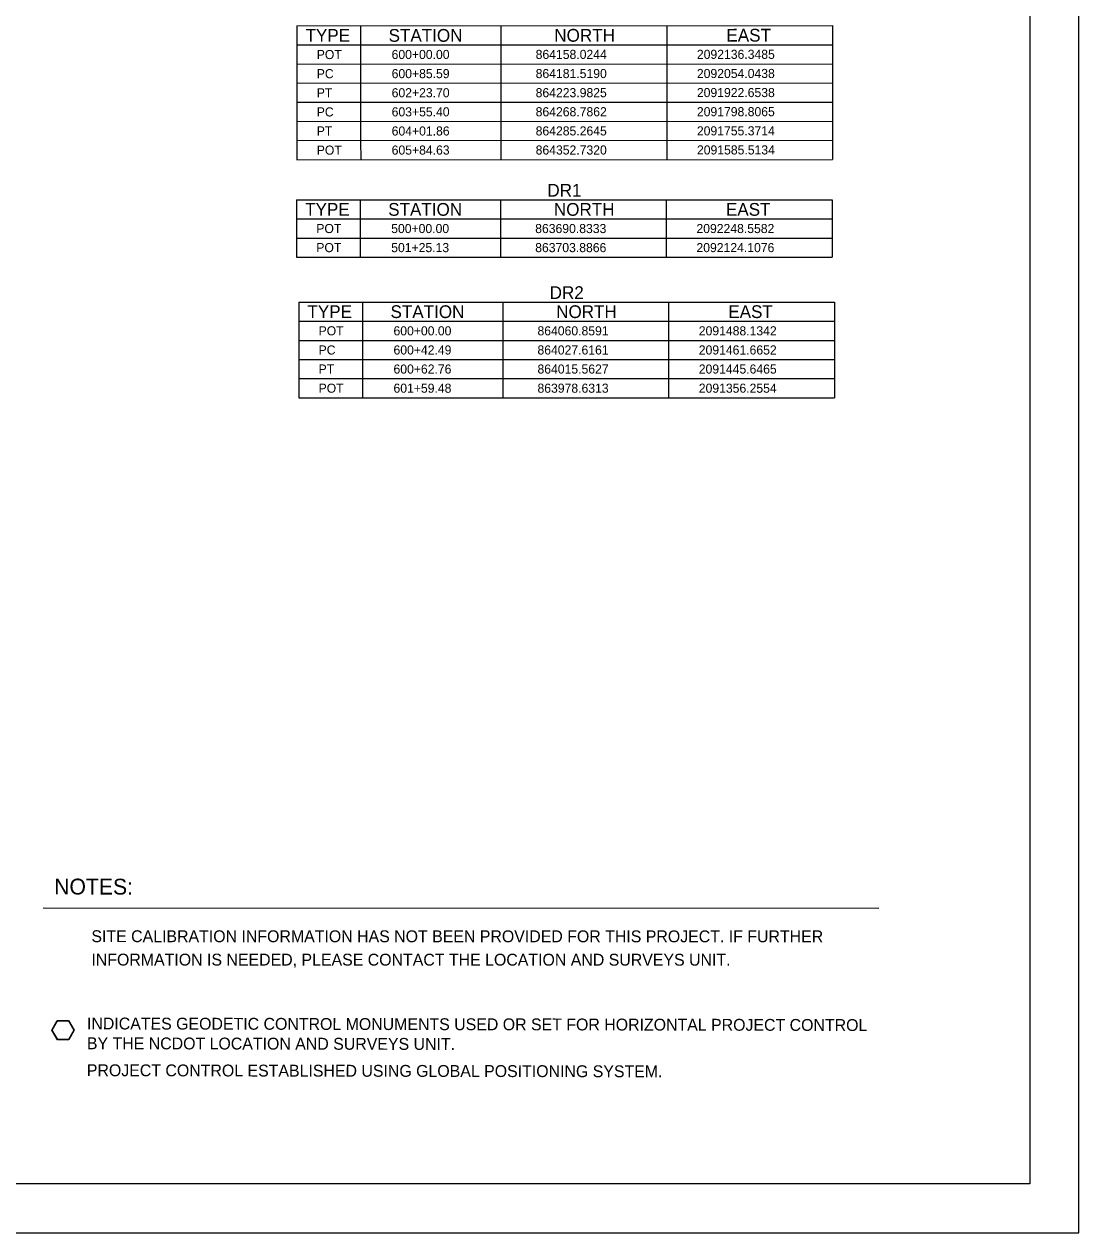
# Model space of a CAD drawing. Extents: x 2093228 to 2098328, y 861854 to 865154.
# Drawn here: x 2096710 to 2098328, y 861854 to 863710 of the extents above; entities that cross this region are included whole.
import ezdxf

# ---------------------------------------------------------------- set-up
doc = ezdxf.new("R2010")
doc.units = 0
for name, color, linetype in [('CTL Primary Horizontal and Vertical CELL', 7, 'Continuous'), ('CTL Sheet Notes CELL', 7, 'Continuous'), ('CTL Sheet Table Cell', 7, 'Continuous'), ('CTL Sheet Text', 7, 'Continuous'), ('Default', 7, 'Continuous'), ('Sheet Plan CELL', 7, 'Continuous'), ('Sheet Plot Border Inside CELL', 7, 'Continuous')]:
    doc.layers.add(name, color=color, linetype=linetype)

msp = doc.modelspace()

# ---------------------------------------------------------------- linework, layer by layer
at = {"layer": 'CTL Primary Horizontal and Vertical CELL'}
msp.add_line((2096769.3, 862165.3), (2096769.3, 862165.3), dxfattribs=at)
msp.add_lwpolyline([(2096777.8, 862180.2), (2096786.3, 862165.4), (2096778.1, 862150.4), (2096761, 862150.5), (2096752.3, 862165.4), (2096760.5, 862180.1)], close=True, dxfattribs=at)
at = {"layer": 'CTL Sheet Notes CELL'}
msp.add_line((2096739, 862353.2), (2098021.6, 862352.9), dxfattribs=at)
at = {"layer": 'CTL Sheet Table Cell'}
for p, q in [((2097128.2, 863707.7), (2097950.3, 863708.1)), ((2097128.2, 863707.7), (2097128.2, 863678.4)), ((2097226.1, 863707.8), (2097226.1, 863678.4)), ((2097441.4, 863707.9), (2097441.4, 863678.5)), ((2097695.8, 863708), (2097695.9, 863678.6)), ((2097950.3, 863708.1), (2097950.3, 863678.8)), ((2097128.2, 863678.4), (2097950.3, 863678.8)), ((2097128.2, 863678.4), (2097128.2, 863649)), ((2097226.1, 863678.4), (2097226.1, 863649.1)), ((2097441.4, 863678.5), (2097441.4, 863649.2)), ((2097695.9, 863678.6), (2097695.9, 863649.3)), ((2097950.3, 863678.8), (2097950.3, 863649.4)), ((2097128.2, 863649), (2097950.3, 863649.4)), ((2097128.2, 863649), (2097128.2, 863619.6)), ((2097226.1, 863649.1), (2097226.1, 863619.7)), ((2097441.4, 863649.2), (2097441.4, 863619.8)), ((2097695.9, 863649.3), (2097695.9, 863619.9)), ((2097950.3, 863649.4), (2097950.4, 863620)), ((2097128.2, 863619.6), (2097950.4, 863620)), ((2097128.2, 863619.6), (2097128.2, 863590.3)), ((2097226.1, 863619.7), (2097226.1, 863590.3)), ((2097441.4, 863619.8), (2097441.4, 863590.4)), ((2097695.9, 863619.9), (2097695.9, 863590.6)), ((2097950.4, 863620), (2097950.4, 863590.7)), ((2097128.2, 863590.3), (2097950.4, 863590.7)), ((2097128.2, 863590.3), (2097128.3, 863560.9)), ((2097226.1, 863590.3), (2097226.1, 863561)), ((2097441.4, 863590.4), (2097441.5, 863561.1)), ((2097695.9, 863590.6), (2097695.9, 863561.2)), ((2097950.4, 863590.7), (2097950.4, 863561.3)), ((2097128.3, 863560.9), (2097950.4, 863561.3)), ((2097441.5, 863561.1), (2097441.5, 863531.7)), ((2097695.9, 863561.2), (2097695.9, 863531.8)), ((2097950.4, 863561.3), (2097950.4, 863532)), ((2097128.3, 863560.9), (2097128.3, 863531.6)), ((2097226.1, 863561), (2097226.1, 863531.6)), ((2097128.3, 863531.6), (2097950.4, 863532)), ((2097128.3, 863531.6), (2097128.3, 863502.2)), ((2097226.1, 863531.6), (2097226.2, 863502.2)), ((2097441.5, 863531.7), (2097441.5, 863502.3)), ((2097695.9, 863531.8), (2097695.9, 863502.5)), ((2097950.4, 863532), (2097950.4, 863502.6)), ((2097128.3, 863502.2), (2097950.4, 863502.6)), ((2097127.6, 863440.6), (2097949.7, 863440.6)), ((2097127.6, 863440.6), (2097127.6, 863411.2)), ((2097225.4, 863440.6), (2097225.4, 863411.2)), ((2097440.7, 863440.6), (2097440.7, 863411.2)), ((2097695.2, 863440.6), (2097695.2, 863411.2)), ((2097949.7, 863440.6), (2097949.7, 863411.2)), ((2097127.6, 863411.2), (2097949.7, 863411.2)), ((2097127.6, 863411.2), (2097127.6, 863381.9)), ((2097225.4, 863411.2), (2097225.4, 863381.9)), ((2097440.7, 863411.2), (2097440.7, 863381.9)), ((2097695.2, 863411.2), (2097695.2, 863381.9)), ((2097949.7, 863411.2), (2097949.7, 863381.9)), ((2097127.6, 863381.9), (2097949.7, 863381.9)), ((2097127.6, 863381.9), (2097127.6, 863352.5)), ((2097225.4, 863381.9), (2097225.4, 863352.5)), ((2097440.7, 863381.9), (2097440.7, 863352.5)), ((2097695.2, 863381.9), (2097695.2, 863352.5)), ((2097949.7, 863381.9), (2097949.7, 863352.5)), ((2097127.6, 863352.5), (2097949.7, 863352.5)), ((2097131.1, 863283.4), (2097953.2, 863283.4)), ((2097131.1, 863283.4), (2097131.1, 863254.1)), ((2097228.9, 863283.4), (2097228.9, 863254.1)), ((2097444.3, 863283.4), (2097444.3, 863254.1)), ((2097698.7, 863283.4), (2097698.7, 863254.1)), ((2097953.2, 863283.4), (2097953.2, 863254.1)), ((2097131.1, 863254.1), (2097953.2, 863254.1)), ((2097131.1, 863254.1), (2097131.1, 863224.7)), ((2097228.9, 863254.1), (2097228.9, 863224.7)), ((2097444.3, 863254.1), (2097444.3, 863224.7)), ((2097698.7, 863254.1), (2097698.7, 863224.7)), ((2097953.2, 863254.1), (2097953.2, 863224.7)), ((2097131.1, 863224.7), (2097953.2, 863224.7)), ((2097131.1, 863224.7), (2097131.1, 863195.3)), ((2097228.9, 863224.7), (2097228.9, 863195.3)), ((2097444.3, 863224.7), (2097444.3, 863195.3)), ((2097698.7, 863224.7), (2097698.7, 863195.3)), ((2097953.2, 863224.7), (2097953.2, 863195.3)), ((2097131.1, 863195.3), (2097953.2, 863195.3)), ((2097131.1, 863195.3), (2097131.1, 863166)), ((2097228.9, 863195.3), (2097228.9, 863166)), ((2097444.3, 863195.3), (2097444.3, 863166)), ((2097698.7, 863195.3), (2097698.7, 863166)), ((2097953.2, 863195.3), (2097953.2, 863166)), ((2097131.1, 863166), (2097953.2, 863166)), ((2097131.1, 863166), (2097131.1, 863136.6)), ((2097228.9, 863166), (2097228.9, 863136.6)), ((2097444.3, 863166), (2097444.3, 863136.6)), ((2097698.7, 863166), (2097698.7, 863136.6)), ((2097953.2, 863166), (2097953.2, 863136.6)), ((2097131.1, 863136.6), (2097953.2, 863136.6))]:
    msp.add_line(p, q, dxfattribs=at)
at = {"layer": 'Default'}
msp.add_line((2096769.3, 862165.3), (2096769.3, 862165.3), dxfattribs=at)
msp.add_lwpolyline([(2096761.1, 862150.9), (2096752.6, 862165.2), (2096760.8, 862179.6), (2096777.5, 862179.8), (2096786, 862165.5), (2096777.8, 862150.9), (2096761.1, 862150.9)], dxfattribs=at)
at = {"layer": 'Sheet Plan CELL'}
msp.add_lwpolyline([(2093753.4, 865079.1), (2098253.4, 865079.1), (2098253.4, 861929.1), (2093753.4, 861929.1)], close=True, dxfattribs=at)
at = {"layer": 'Sheet Plot Border Inside CELL'}
msp.add_lwpolyline([(2098328.4, 865154.1), (2093228.4, 865154.1), (2093228.4, 861854.1), (2098328.4, 861854.1)], close=True, dxfattribs=at)

# ---------------------------------------------------------------- texts
at = {"layer": 'CTL Sheet Notes CELL'}
for s, height, rotation, p in [('TYPE', 19.57, 0.0276, (2097141.5, 863683.3)), ('STATION', 19.57, 0.0276, (2097269, 863683.3)), ('NORTH', 19.57, 0.0276, (2097523.3, 863683.4)), ('EAST', 19.57, 0.0276, (2097787.5, 863683.6)), ('NOTES:', 24.32, 359.8816, (2096755.6, 862373.8)), ('SITE CALIBRATION INFORMATION HAS NOT BEEN PROVIDED FOR THIS PROJECT. IF FURTHER', 18.237, 359.9869, (2096812.8, 862300.5)), ('INFORMATION IS NEEDED, PLEASE CONTACT THE LOCATION AND SURVEYS UNIT.', 18.237, 359.9869, (2096812.8, 862264.6)), ('INDICATES GEODETIC CONTROL MONUMENTS USED OR SET FOR HORIZONTAL PROJECT CONTROL', 18.237, 359.8816, (2096806, 862166.5)), ('BY THE NCDOT LOCATION AND SURVEYS UNIT.', 18.237, 359.8816, (2096805.9, 862136.1)), ('PROJECT CONTROL ESTABLISHED USING GLOBAL POSITIONING SYSTEM.', 18.237, 359.8816, (2096805.8, 862094.7))]:
    msp.add_text(s, height=height, rotation=rotation, dxfattribs=at).set_placement(p)
for s, p in [('DR1', (2097512.7, 863445.5)), ('TYPE', (2097140.9, 863416.1)), ('STATION', (2097268.4, 863416.1)), ('NORTH', (2097522.7, 863416.1)), ('EAST', (2097786.8, 863416.1)), ('DR2', (2097516.2, 863288.3)), ('TYPE', (2097144.4, 863259)), ('STATION', (2097271.9, 863259)), ('NORTH', (2097526.2, 863259)), ('EAST', (2097790.4, 863259))]:
    msp.add_text(s, height=19.57, dxfattribs=at).set_placement(p)
at = {"layer": 'CTL Sheet Text'}
for s, height, p in [('POT', 13.98, (2097158.7, 863656.7)), ('600+00.00', 13.98, (2097273.6, 863656.8)), ('864158.0244', 13.982, (2097494.7, 863656.9)), ('2092136.3485', 13.982, (2097742.2, 863657)), ('PC ', 13.98, (2097158.7, 863627.3)), ('600+85.59', 13.98, (2097273.7, 863627.4)), ('864181.5190', 13.982, (2097494.7, 863627.5)), ('2092054.0438', 13.982, (2097742.2, 863627.6)), ('PT ', 13.98, (2097158.7, 863598)), ('602+23.70', 13.98, (2097273.7, 863598)), ('864223.9825', 13.982, (2097494.7, 863598.1)), ('2091922.6538', 13.982, (2097742.2, 863598.3)), ('PC ', 13.98, (2097158.7, 863568.6)), ('603+55.40', 13.98, (2097273.7, 863568.7)), ('864268.7862', 13.982, (2097494.7, 863568.8)), ('2091798.8065', 13.982, (2097742.2, 863568.9)), ('PT ', 13.98, (2097158.7, 863539.3)), ('604+01.86', 13.98, (2097273.7, 863539.3)), ('864285.2645', 13.982, (2097494.7, 863539.4)), ('2091755.3714', 13.982, (2097742.2, 863539.5)), ('POT', 13.98, (2097158.7, 863509.9)), ('605+84.63', 13.98, (2097273.7, 863510)), ('864352.7320', 13.982, (2097494.7, 863510.1)), ('2091585.5134', 13.982, (2097742.3, 863510.2))]:
    msp.add_text(s, height=height, rotation=0.0276, dxfattribs=at).set_placement(p)
for s, height, p in [('POT', 13.98, (2097158, 863389.5)), ('500+00.00', 13.98, (2097273, 863389.5)), ('863690.8333', 13.982, (2097494, 863389.5)), ('2092248.5582', 13.982, (2097741.5, 863389.5)), ('POT', 13.98, (2097158, 863360.2)), ('501+25.13', 13.98, (2097273, 863360.2)), ('863703.8866', 13.982, (2097494, 863360.2)), ('2092124.1076', 13.982, (2097741.5, 863360.2)), ('POT', 13.98, (2097161.5, 863232.4)), ('600+00.00', 13.98, (2097276.5, 863232.4)), ('864060.8591', 13.982, (2097497.5, 863232.4)), ('2091488.1342', 13.982, (2097745.1, 863232.4)), ('PC ', 13.98, (2097161.5, 863203)), ('600+42.49', 13.98, (2097276.5, 863203)), ('864027.6161', 13.982, (2097497.5, 863203)), ('2091461.6652', 13.982, (2097745.1, 863203)), ('PT ', 13.98, (2097161.5, 863173.7)), ('600+62.76', 13.98, (2097276.5, 863173.7)), ('864015.5627', 13.982, (2097497.5, 863173.7)), ('2091445.6465', 13.982, (2097745.1, 863173.7)), ('POT', 13.98, (2097161.5, 863144.3)), ('601+59.48', 13.98, (2097276.5, 863144.3)), ('863978.6313', 13.982, (2097497.5, 863144.3)), ('2091356.2554', 13.982, (2097745.1, 863144.3))]:
    msp.add_text(s, height=height, dxfattribs=at).set_placement(p)

doc.saveas('drawing.dxf')
